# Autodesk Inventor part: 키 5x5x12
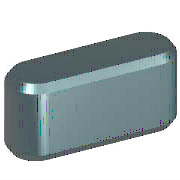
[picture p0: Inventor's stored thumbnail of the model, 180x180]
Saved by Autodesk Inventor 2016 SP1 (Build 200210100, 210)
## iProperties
IsCustomPart: 1
Created: 2012-02
Part Number: 키 5x5x12
Material: 강철, 연강
Description: 키 및 해당 키홈
Document SubType Name: Modeling
Standard: KS B 1311
Designer: mduedu
Standards Organization: KS
Language: ko-KR
Size Designation: 5 x 5 x 12
Categories: <MemberInstance><Categories><Category DisplayName="샤프트 부품" InternalName="7f7aeb1f-a693-4053-b835-cee3144e0d98" Mnemonic="SHFT"><Category DisplayName="키" Interna
Density: 1 g/cm^3
Appearance: 노란색
Author: mduedu
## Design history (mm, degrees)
workplane "Work Plane1"
workplane "Work Plane2"
sketch "스케치1"
  geometry: L1 (2.5, 2.5)-(9.5, 2.5); L2 (9.5, -2.5)-(2.5, -2.5); L3 (0, 9.4)-(0, -7.4) reference; L4 (-5, 0)-(30, 0) reference; L5 (12, 0)-(12, 7); A1 r 2.5 centre (2.5, 0) between (2.5, 2.5) and (2.5, -2.5); A2 r 2.5 centre (9.5, 0) between (9.5, -2.5) and (9.5, 2.5)
  constraints: 6 end point, 5 point on circle, 4 tangent, 3 point on line, 2 centre point, 1 horizontal, 1 parallel, 1 perpendicular
  dimensions: "d0" = 2.5 radius of A1 (= 0.5 x PB); "d13" = 2.5 radius of A2 (= 0.5 x PB); "d14" = 12 distance between parallel lines of L5 L3 (= NLG)
extrude "본체1" new body sketch "스케치1" taper "d3" = 0 deg; stored distance "d4" = 10
workplane "Work Plane3"
body "Solid1"
chamfer "모따기1" distance "d8" = 0.4 (= PHH); stored, may be unused: second distance "d9" = 0.4 (= PHH), angle "d15" = 45 deg
other parameters: "d1" = -3 (= -PNT), "d2" = 2 (= PH - PNT), "NLG" = 12 [user parameter; used in 3 equation terms], "PB" = 5 [user parameter; used in 2 equation terms], "PNT" = 3 [user parameter; used in 2 equation terms], "PH" = 5 [user parameter; used in 1 equation term], "PHH" = 0.4 [user parameter; used in 2 equation terms], "d10" = 0, "d16" = 0, "d17" = 0, "d18" = 0, "WDMIN" = 12 [user parameter], "PLB2" = 12 (= NLG) [user parameter], "WDMAX" = 17 [user parameter], "PLB1" = 12 (= NLG) [user parameter], "RR" = 0.16 [user parameter], "PUEB" = 2.3 [user parameter]
